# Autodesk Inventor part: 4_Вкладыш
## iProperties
Created: 2009-12
Part Number: 4_Вкладыш
Document SubType Name: Modeling
Designer: Jeck
Density: 1 g/cm^3
Mass: 46.9578 g
Surface Area: 132.327 cm^2
Volume: 46.9578 cm^3
Author: Jeck
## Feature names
1. Выдавливание1 [Extrusion]
2. Отверстие1 [Hole]
